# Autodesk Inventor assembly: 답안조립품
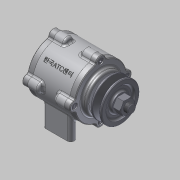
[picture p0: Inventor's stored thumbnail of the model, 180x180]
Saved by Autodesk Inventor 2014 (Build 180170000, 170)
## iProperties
Created: 2015-03
Part Number: 답안조립품
Document SubType Name: Assembly
Designer: MYHOME
Author: MYHOME
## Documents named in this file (11)
- C:\Documents and Settings\MYHOME\바탕 화면\450306V1012\답안조립품.iam
- C:\Documents and Settings\MYHOME\바탕 화면\450306V1012\본체.ipt
- C:\Documents and Settings\MYHOME\바탕 화면\450306V1012\커버.ipt
- C:\Documents and Settings\MYHOME\바탕 화면\450306V1012\커버2.ipt
- C:\Documents and Settings\MYHOME\바탕 화면\450306V1012\축.ipt
- C:\Documents and Settings\MYHOME\바탕 화면\450306V1012\베어링 6204.ipt
- C:\Documents and Settings\MYHOME\바탕 화면\450306V1012\오일실.ipt
- C:\Documents and Settings\MYHOME\바탕 화면\450306V1012\V벨트풀리.ipt
- C:\Documents and Settings\MYHOME\바탕 화면\450306V1012\키(4 x 4 x 12).ipt
- C:\Documents and Settings\MYHOME\바탕 화면\450306V1012\M 4 x 12.ipt
- C:\Documents and Settings\MYHOME\바탕 화면\450306V1012\너트 M12x1.25.ipt
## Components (14 placed, 6 different names)
1. KS B 2023 6204 - 20 x 47 x 14:1 — 각도:1
2. KS B 2023 6204 - 20 x 47 x 14:2 — 각도:2
3. KS B 2804 D D - 20 32 8:1
4. 그루브 풀리1:1
5. KS B 1311 (I) 4 x 4 x 12:1
6. KS B 1012 클래스 1 일반 - 미터 M12x1.25:1 — 각도:4
7. KS B 1003 - 미터 M 4 x 12:1
8. KS B 1003 - 미터 M 4 x 12:3
9. KS B 1003 - 미터 M 4 x 12:4
10. KS B 1003 - 미터 M 4 x 12:5
11. KS B 1003 - 미터 M 4 x 12:2
12. KS B 1003 - 미터 M 4 x 12:6
13. KS B 1003 - 미터 M 4 x 12:7
14. KS B 1003 - 미터 M 4 x 12:8
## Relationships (3: Angle 3)
- 각도:1 [Angle]: KS B 2023 6204 - 20 x 47 x 14:1
- 각도:2 [Angle]: KS B 2023 6204 - 20 x 47 x 14:2
- 각도:4 [Angle]: KS B 1012 클래스 1 일반 - 미터 M12x1.25:1
